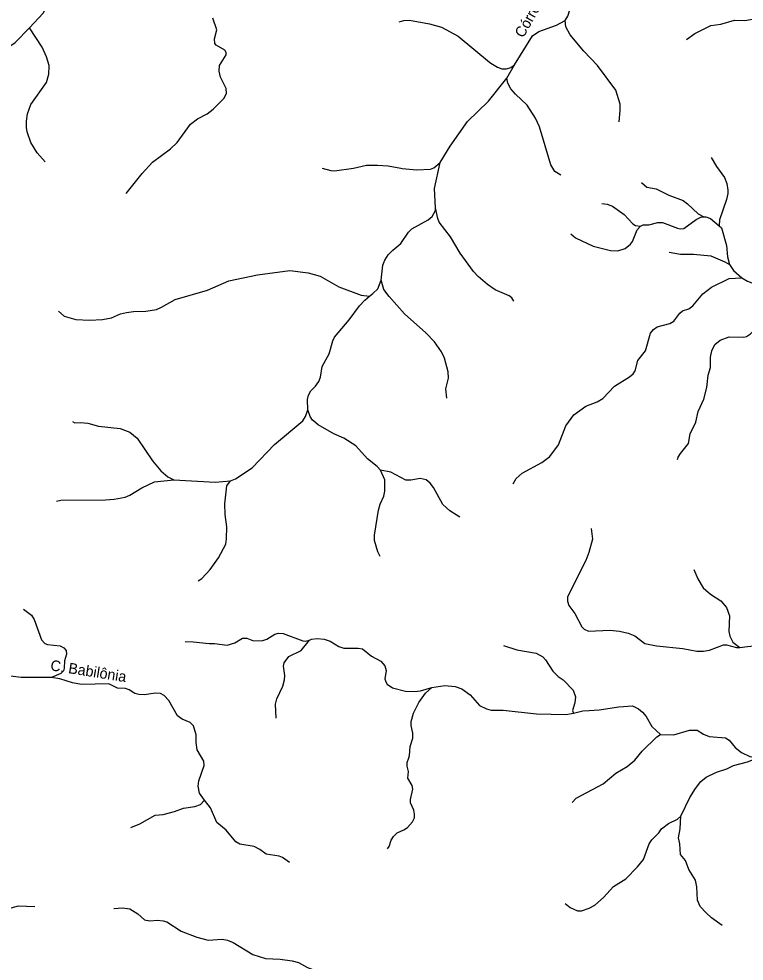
# Model space of a CAD drawing. Extents: x 473.9 to 500, y 7733.1 to 7760.8.
# Drawn here: x 481.99 to 487.45, y 7741.31 to 7748.41 of the extents above; entities that cross this region are included whole.
import ezdxf
from ezdxf.enums import TextEntityAlignment as Align

# ---------------------------------------------------------------- set-up
doc = ezdxf.new("R2010")
doc.units = 0
doc.header["$LTSCALE"] = 0.032
doc.layers.add('61', color=7, linetype='Continuous')
doc.layers.add('7', color=7, linetype='Continuous', lineweight=25)

msp = doc.modelspace()

# ---------------------------------------------------------------- linework, layer by layer
at = {"layer": '7'}
msp.add_line((485.6657, 7747.9601), (485.7235, 7748.059), dxfattribs=at)
for points in [[(482.0709, 7748.3392), (482.1724, 7748.4494), (482.2191, 7748.5344), (482.2567, 7748.7095), (482.2852, 7748.8048), (482.3234, 7748.9022), (482.3735, 7748.9927), (482.4026, 7749.0943), (482.4125, 7749.1288), (482.4697, 7749.2448), (482.5611, 7749.4699), (482.8029, 7749.7518), (482.8852, 7749.8245), (482.9562, 7749.915), (483.033, 7749.996), (483.0934, 7750.0378)], [(486.1039, 7748.3931), (486.126, 7748.4265), (486.1396, 7748.4732), (486.1532, 7748.5626), (486.1581, 7748.6544), (486.1533, 7748.8298), (486.1684, 7748.907), (486.2202, 7749.0114), (486.3188, 7749.1595)], [(487.0191, 7748.2502), (487.0804, 7748.2965), (487.2027, 7748.3564), (487.2773, 7748.3661), (487.3794, 7748.3957), (487.4572, 7748.3934), (487.5013, 7748.4013), (487.615, 7748.4076), (487.6676, 7748.4312), (487.7, 7748.4595)], [(482.7989, 7747.091), (482.9192, 7747.2406), (482.9962, 7747.3258), (483.1313, 7747.4264), (483.1816, 7747.4742), (483.2826, 7747.6137), (483.3348, 7747.6528), (483.4092, 7747.69), (483.4542, 7747.7253), (483.5343, 7747.8062), (483.5554, 7747.845), (483.551, 7747.8823), (483.5102, 7747.9667), (483.4977, 7748.0117), (483.5015, 7748.0559), (483.552, 7748.135), (483.5522, 7748.1524), (483.5407, 7748.1707), (483.4758, 7748.2084), (483.4673, 7748.2213), (483.4641, 7748.257), (483.4801, 7748.3227), (483.4505, 7748.4106)], [(484.8535, 7748.3833), (484.8909, 7748.3941), (484.9313, 7748.3973), (485.0833, 7748.3677), (485.1741, 7748.3434), (485.2991, 7748.2756), (485.5358, 7748.0801), (485.5452, 7748.0723), (485.596, 7748.0418), (485.6276, 7748.0302), (485.6635, 7748.0307), (485.6969, 7748.0389), (485.7235, 7748.059)], [(485.7235, 7748.059), (485.8587, 7748.2777), (485.9071, 7748.3115), (486.0397, 7748.3581), (486.1039, 7748.3931)], [(486.5116, 7747.6293), (486.5204, 7747.715), (486.5188, 7747.7647), (486.4874, 7747.8694), (486.3483, 7748.0555), (486.2444, 7748.1628), (486.143, 7748.2871), (486.1103, 7748.3463), (486.1039, 7748.3931)], [(481.7151, 7747.8935), (481.7306, 7747.902), (481.7418, 7747.9179), (481.8131, 7748.078), (481.8468, 7748.1401), (481.8712, 7748.1642), (481.962, 7748.227), (482.0709, 7748.3392)], [(482.1896, 7747.3284), (482.1274, 7747.3957), (482.0805, 7747.4738), (482.053, 7747.5547), (482.0466, 7747.5868), (482.0466, 7747.6358), (482.0546, 7747.6909), (482.0804, 7747.7602), (482.1975, 7747.9272), (482.2149, 7747.9905), (482.2189, 7748.0507), (482.2177, 7748.0548), (482.1986, 7748.1198), (482.1664, 7748.1922), (482.0709, 7748.3392)], [(485.1625, 7747.3234), (485.2377, 7747.4478), (485.3705, 7747.6338), (485.5276, 7747.7853), (485.6657, 7747.9601)], [(486.0735, 7747.2288), (486.0261, 7747.2552), (485.9964, 7747.3071), (485.9108, 7747.5916), (485.8806, 7747.6572), (485.8187, 7747.7562), (485.7297, 7747.8395), (485.6948, 7747.8799), (485.6741, 7747.9223), (485.6657, 7747.9601)], [(487.2043, 7747.3617), (487.2443, 7747.2939), (487.3046, 7747.2116), (487.3215, 7747.1647), (487.3302, 7747.1155), (487.3303, 7747.0915), (487.3191, 7747.045), (487.267, 7746.8926), (487.2646, 7746.8488), (487.2645, 7746.8475)], [(484.2749, 7747.2816), (484.3393, 7747.2629), (484.3679, 7747.2621), (484.5115, 7747.2821), (484.6094, 7747.303), (484.6923, 7747.3046), (484.7729, 7747.2996), (484.8676, 7747.2806), (484.8762, 7747.2789), (484.988, 7747.2693), (485.0912, 7747.2734), (485.1165, 7747.2833), (485.1625, 7747.3234)], [(485.1284, 7746.9822), (485.1205, 7747.1281), (485.1625, 7747.3234)], [(486.6789, 7747.1723), (486.7209, 7747.1386), (486.7911, 7747.1249), (486.8855, 7747.0783), (486.9925, 7747.0388), (487.027, 7747.0136), (487.1068, 7746.9363), (487.1501, 7746.914)], [(486.3813, 7747.0145), (486.4224, 7747.0108), (486.4625, 7746.9944), (486.5505, 7746.9328), (486.6134, 7746.8609), (486.635, 7746.85), (486.6721, 7746.8451)], [(484.7181, 7746.4386), (484.7326, 7746.5496), (484.746, 7746.5874), (484.771, 7746.6273), (484.806, 7746.6644), (484.8665, 7746.7129), (484.9255, 7746.7991), (484.951, 7746.824), (485.0727, 7746.8933), (485.1027, 7746.9178), (485.1279, 7746.962), (485.1284, 7746.9822)], [(485.7178, 7746.2781), (485.7026, 7746.3044), (485.682, 7746.3201), (485.5772, 7746.3658), (485.5193, 7746.4041), (485.4493, 7746.4642), (485.4151, 7746.5017), (485.3133, 7746.6397), (485.2416, 7746.764), (485.1565, 7746.8734), (485.1448, 7746.9013), (485.1284, 7746.9822)], [(486.6721, 7746.8451), (486.6921, 7746.8553), (486.7349, 7746.854), (486.804, 7746.8731), (486.8379, 7746.8731), (486.9505, 7746.8289), (486.9723, 7746.8235), (486.9979, 7746.8265), (487.0911, 7746.8957), (487.1265, 7746.9115), (487.1501, 7746.914)], [(487.1501, 7746.914), (487.1646, 7746.9155), (487.1989, 7746.9028), (487.2645, 7746.8475)], [(486.1466, 7746.7857), (486.183, 7746.7577), (486.3155, 7746.6935), (486.4454, 7746.6598), (486.5017, 7746.6589), (486.556, 7746.6761), (486.5972, 7746.7093), (486.611, 7746.7288), (486.6472, 7746.816), (486.6721, 7746.8451)], [(487.2645, 7746.8475), (487.2837, 7746.8313), (487.3207, 7746.6996), (487.3287, 7746.6127), (487.3429, 7746.5548)], [(486.8887, 7746.6487), (486.9749, 7746.6327), (487.0708, 7746.6343), (487.2033, 7746.6198), (487.3065, 7746.5763), (487.3429, 7746.5548)], [(482.2896, 7746.2045), (482.3309, 7746.1673), (482.4202, 7746.1404), (482.5211, 7746.1355), (482.6199, 7746.1404), (482.689, 7746.1545), (482.7548, 7746.1844), (482.8018, 7746.1948), (482.8526, 7746.202), (482.9461, 7746.2029), (483.026, 7746.2172), (483.0644, 7746.2331), (483.1671, 7746.2925), (483.4114, 7746.3631), (483.5706, 7746.4331), (483.7873, 7746.4785), (484.0305, 7746.5099), (484.1696, 7746.4939), (484.2601, 7746.468), (484.3999, 7746.3884), (484.5673, 7746.324), (484.6323, 7746.3159)], [(487.3429, 7746.5548), (487.3721, 7746.5113), (487.4365, 7746.4549)], [(484.6323, 7746.3159), (484.6563, 7746.3374), (484.6948, 7746.3721), (484.7181, 7746.4386)], [(485.2132, 7745.548), (485.2056, 7745.6185), (485.2264, 7745.699), (485.2231, 7745.7474), (485.1965, 7745.8507), (485.1728, 7745.8987), (485.1201, 7745.9717), (485.0566, 7746.0415), (484.895, 7746.183), (484.7784, 7746.3143), (484.7388, 7746.3675), (484.7181, 7746.4386)], [(485.7141, 7744.9039), (485.7363, 7744.9431), (485.781, 7744.9836), (485.9289, 7745.0633), (485.9885, 7745.1099), (486.0554, 7745.1975), (486.1096, 7745.3411), (486.1699, 7745.4233), (486.2601, 7745.4889), (486.3462, 7745.5216), (486.3895, 7745.545), (486.4766, 7745.6396), (486.5905, 7745.7083), (486.6174, 7745.7325), (486.6311, 7745.7541), (486.6529, 7745.8311), (486.7096, 7745.9062), (486.7465, 7746.039), (486.7704, 7746.0671), (486.7979, 7746.0851), (486.8933, 7746.1108), (486.9227, 7746.1289), (486.9688, 7746.1893), (486.9897, 7746.2058), (487.0355, 7746.2222), (487.0671, 7746.2435), (487.1416, 7746.3357), (487.2062, 7746.3851), (487.3402, 7746.4491), (487.4365, 7746.4549)], [(487.4365, 7746.4549), (487.4787, 7746.4305), (487.5926, 7746.3836), (487.6609, 7746.3373), (487.7328, 7746.2653)], [(484.1661, 7745.4612), (484.1649, 7745.5396), (484.1711, 7745.5723), (484.1884, 7745.6049), (484.2237, 7745.6379), (484.2503, 7745.6747), (484.2627, 7745.7077), (484.2748, 7745.7862), (484.3277, 7745.8824), (484.3552, 7745.981), (484.3686, 7746.0091), (484.4772, 7746.1385), (484.5559, 7746.2435), (484.5952, 7746.286), (484.6323, 7746.3159)], [(486.9514, 7745.0862), (486.9552, 7745.1044), (486.974, 7745.1325), (487.0331, 7745.206), (487.0468, 7745.2802), (487.0879, 7745.3684), (487.1077, 7745.447), (487.1489, 7745.5419), (487.1731, 7745.6287), (487.1825, 7745.7223), (487.2003, 7745.7808), (487.2004, 7745.858), (487.2104, 7745.9056), (487.2323, 7745.9524), (487.2728, 7745.9865), (487.3399, 7746.0096), (487.4483, 7746.0089), (487.4707, 7746.0142), (487.5, 7746.0343), (487.565, 7746.1024), (487.6346, 7746.2048), (487.6801, 7746.2431), (487.7328, 7746.2653)], [(483.5846, 7744.9259), (483.6222, 7744.9397), (483.7485, 7745.0248), (483.9166, 7745.2), (484.1285, 7745.3776), (484.1503, 7745.4104), (484.1661, 7745.4612)], [(484.7153, 7745.0066), (484.6894, 7745.0346), (484.6168, 7745.0902), (484.5282, 7745.1883), (484.4384, 7745.2459), (484.3617, 7745.2802), (484.244, 7745.3477), (484.2113, 7745.3742), (484.2015, 7745.3821), (484.1831, 7745.4094), (484.1661, 7745.4612)], [(482.3933, 7745.3721), (482.4115, 7745.3624), (482.4554, 7745.3648), (482.509, 7745.3592), (482.5901, 7745.3386), (482.7537, 7745.3192), (482.8258, 7745.2928), (482.8816, 7745.2474), (482.9967, 7745.0766), (483.0587, 7744.9998), (483.1111, 7744.957), (483.1568, 7744.9321)], [(484.7115, 7744.3551), (484.6938, 7744.3899), (484.67, 7744.4758), (484.6684, 7744.5154), (484.6984, 7744.7051), (484.7106, 7744.751), (484.7385, 7744.8096), (484.7478, 7744.8485), (484.7469, 7744.9344), (484.7153, 7745.0066)], [(485.3109, 7744.6528), (485.2352, 7744.6995), (485.1845, 7744.747), (485.1143, 7744.8757), (485.0891, 7744.9072), (485.058, 7744.9328), (485.0123, 7744.9425), (484.9414, 7744.9303), (484.9037, 7744.9313), (484.7909, 7744.9903), (484.7153, 7745.0066)], [(482.2741, 7744.7715), (482.3065, 7744.7805), (482.6423, 7744.7821), (482.7091, 7744.7881), (482.7907, 7744.8035), (482.827, 7744.8187), (482.9172, 7744.8735), (483.0122, 7744.9192), (483.1568, 7744.9321)], [(483.1568, 7744.9321), (483.469, 7744.9167), (483.5846, 7744.9259)], [(483.3398, 7744.1711), (483.3692, 7744.1889), (483.4303, 7744.2583), (483.495, 7744.3463), (483.549, 7744.4494), (483.5554, 7744.4897), (483.5571, 7744.5798), (483.5443, 7744.6727), (483.5427, 7744.752), (483.5573, 7744.887), (483.5846, 7744.9259)], [(486.3004, 7744.5664), (486.3112, 7744.4867), (486.2835, 7744.3855), (486.2604, 7744.326), (486.1228, 7744.0524), (486.1221, 7744.0194), (486.1325, 7743.9859), (486.1769, 7743.9268), (486.2317, 7743.8253), (486.2489, 7743.8075), (486.2805, 7743.7926), (486.4413, 7743.7999), (486.5131, 7743.7934), (486.5792, 7743.7792), (486.6293, 7743.7573), (486.7053, 7743.7011), (486.7924, 7743.6821), (486.9916, 7743.6621), (487.0971, 7743.6436), (487.1464, 7743.642), (487.1929, 7743.6497), (487.2963, 7743.69), (487.3206, 7743.69), (487.3949, 7743.6701), (487.4196, 7743.6711)], [(487.0734, 7744.2585), (487.1043, 7744.1866), (487.1456, 7744.1185), (487.2006, 7744.0716), (487.2771, 7744.0222), (487.3195, 7743.9705), (487.3416, 7743.9094), (487.3383, 7743.79), (487.346, 7743.7558), (487.3676, 7743.7106), (487.4196, 7743.6711)], [(482.0261, 7743.9583), (482.0845, 7743.9134), (482.1046, 7743.8799), (482.1602, 7743.7272), (482.186, 7743.7013), (482.2063, 7743.693), (482.3022, 7743.6834), (482.3298, 7743.6674), (482.3456, 7743.6476), (482.3496, 7743.6191), (482.3344, 7743.5685), (482.3319, 7743.5137), (482.3255, 7743.4945), (482.3056, 7743.4741), (482.2368, 7743.4441)], [(483.2428, 7743.7148), (483.3043, 7743.7133), (483.4238, 7743.6989), (483.463, 7743.7004), (483.559, 7743.6869), (483.6161, 7743.706), (483.6754, 7743.7399), (483.7068, 7743.7396), (483.7587, 7743.7214), (483.8278, 7743.7224), (483.8591, 7743.7336), (483.9171, 7743.7715), (483.9453, 7743.7783), (483.982, 7743.7758), (484.1287, 7743.7209), (484.1469, 7743.7177), (484.1805, 7743.7242)], [(484.1805, 7743.7242), (484.1956, 7743.7319), (484.2367, 7743.7381), (484.2896, 7743.7334), (484.3348, 7743.7166), (484.3999, 7743.6775), (484.4387, 7743.6653), (484.5462, 7743.6661), (484.5785, 7743.6596), (484.6466, 7743.6044), (484.7158, 7743.5662), (484.7461, 7743.5321), (484.7566, 7743.4956), (484.747, 7743.435), (484.7539, 7743.4117), (484.7639, 7743.3934), (484.8033, 7743.3668), (484.9033, 7743.3405), (484.9689, 7743.3373), (485.0153, 7743.3427), (485.1012, 7743.3679)], [(483.9284, 7743.137), (483.9228, 7743.2429), (483.9329, 7743.2821), (483.9786, 7743.3783), (483.9916, 7743.4273), (483.9932, 7743.4594), (483.9845, 7743.5303), (483.988, 7743.5544), (484.0248, 7743.602), (484.1164, 7743.6478), (484.1805, 7743.7242)], [(485.6393, 7743.6857), (485.7417, 7743.6533), (485.8867, 7743.6268), (485.9378, 7743.6008), (485.958, 7743.5776), (486.0114, 7743.4906), (486.0512, 7743.4522), (486.0894, 7743.4268), (486.1656, 7743.3495), (486.1822, 7743.2991), (486.1783, 7743.253), (486.1597, 7743.1965), (486.167, 7743.1758)], [(487.4196, 7743.6711), (487.4771, 7743.677), (487.5563, 7743.6852), (487.6237, 7743.6844), (487.7049, 7743.6717), (487.8022, 7743.6311), (487.9952, 7743.5831), (488.0989, 7743.5365), (488.1381, 7743.5258), (488.1824, 7743.5234), (488.2518, 7743.537), (488.2972, 7743.5291)], [(482.2368, 7743.4441), (482.0066, 7743.4435), (481.8239, 7743.4671), (481.5727, 7743.476), (481.4942, 7743.4897), (481.3935, 7743.496), (481.3486, 7743.4871), (481.273, 7743.4428), (481.2278, 7743.4288)], [(483.3882, 7742.5188), (483.352, 7742.5721), (483.3406, 7742.6265), (483.3468, 7742.6643), (483.3855, 7742.7808), (483.3839, 7742.8145), (483.3327, 7742.8978), (483.3246, 7742.9534), (483.3245, 7743.012), (483.3053, 7743.0791), (483.2797, 7743.1046), (483.221, 7743.1301), (483.1856, 7743.154), (483.1195, 7743.2713), (483.0854, 7743.3095), (483.0574, 7743.3242), (483.0177, 7743.326), (482.937, 7743.3144), (482.8929, 7743.3149), (482.8646, 7743.3235), (482.8557, 7743.3292), (482.82, 7743.3521), (482.7929, 7743.3604), (482.7341, 7743.3646), (482.6667, 7743.3969), (482.4619, 7743.391), (482.3942, 7743.4047), (482.2994, 7743.4348), (482.2368, 7743.4441)], [(485.1012, 7743.3679), (485.1984, 7743.3845), (485.2758, 7743.3774), (485.3277, 7743.358), (485.3905, 7743.3143), (485.46, 7743.2336), (485.5122, 7743.2073), (485.5484, 7743.1987), (485.6381, 7743.1969), (485.8892, 7743.1691), (486.1112, 7743.1657), (486.167, 7743.1758)], [(484.7665, 7742.1537), (484.7782, 7742.1706), (484.7933, 7742.2178), (484.8116, 7742.2458), (484.8405, 7742.2726), (484.8894, 7742.2952), (484.9167, 7742.3148), (484.954, 7742.357), (484.9698, 7742.3867), (484.9714, 7742.4155), (484.9652, 7742.4435), (484.941, 7742.5003), (484.9411, 7742.5248), (484.9586, 7742.603), (484.9517, 7742.6295), (484.9204, 7742.6868), (484.9249, 7742.7356), (484.9138, 7742.7754), (484.9154, 7742.8038), (484.9275, 7742.8385), (484.9337, 7742.8562), (484.9366, 7742.923), (484.9586, 7742.9862), (484.9586, 7743.0249), (484.9458, 7743.082), (484.9458, 7743.1118), (484.9621, 7743.1759), (485.002, 7743.2555), (485.053, 7743.3258), (485.1012, 7743.3679)], [(486.167, 7743.1758), (486.2382, 7743.1929), (486.2857, 7743.1954), (486.3617, 7743.1993), (486.5096, 7743.2235), (486.6109, 7743.2305), (486.6583, 7743.2082), (486.6886, 7743.182), (486.7139, 7743.1506), (486.7575, 7743.0749), (486.8241, 7743.0156)], [(486.1566, 7742.5033), (486.1889, 7742.5342), (486.3922, 7742.6438), (486.4855, 7742.7244), (486.5721, 7742.7722), (486.6292, 7742.8222), (486.6846, 7742.888), (486.7965, 7742.9975), (486.8241, 7743.0156)], [(486.8241, 7743.0156), (486.9234, 7743.0132), (487.0413, 7743.047), (487.0983, 7743.048), (487.146, 7743.018), (487.1898, 7742.9996), (487.3129, 7742.9884), (487.3397, 7742.971), (487.3862, 7742.9165), (487.4319, 7742.8783), (487.4957, 7742.8481), (487.5561, 7742.838)], [(486.9771, 7742.4003), (487.045, 7742.539), (487.0859, 7742.6079), (487.1266, 7742.6614), (487.167, 7742.6939), (487.245, 7742.7315), (487.3216, 7742.7566), (487.3729, 7742.7822), (487.4788, 7742.8085), (487.5561, 7742.838)], [(482.8331, 7742.3139), (482.9021, 7742.3411), (483.0159, 7742.4069), (483.0764, 7742.4113), (483.1629, 7742.4343), (483.2313, 7742.46), (483.3144, 7742.4728), (483.3572, 7742.4882), (483.3882, 7742.5188)], [(484.0279, 7742.0491), (483.9756, 7742.0873), (483.9505, 7742.0983), (483.8535, 7742.1131), (483.8056, 7742.1482), (483.7615, 7742.1698), (483.6555, 7742.1874), (483.6241, 7742.2047), (483.5524, 7742.2931), (483.4824, 7742.3516), (483.4336, 7742.4617), (483.3882, 7742.5188)], [(486.1051, 7741.7419), (486.1422, 7741.7121), (486.1976, 7741.685), (486.2268, 7741.6864), (486.2866, 7741.7054), (486.3274, 7741.7299), (486.3946, 7741.7866), (486.4685, 7741.8691), (486.5621, 7741.9261), (486.6507, 7742.0172), (486.6943, 7742.0726), (486.7364, 7742.1896), (486.7575, 7742.2201), (486.8109, 7742.2728), (486.8317, 7742.3048), (486.8836, 7742.3434), (486.9515, 7742.3755), (486.9771, 7742.4003)], [(487.2886, 7741.5761), (487.2063, 7741.6333), (487.1667, 7741.6712), (487.1225, 7741.7195), (487.1007, 7741.767), (487.0961, 7741.8671), (487.0865, 7741.9179), (487.0365, 7741.9982), (487.0125, 7742.0644), (486.9746, 7742.1102), (486.9694, 7742.1917), (486.9575, 7742.2367), (486.9703, 7742.3036), (486.9771, 7742.4003)], [(482.1099, 7741.7153), (481.984, 7741.7217), (481.7828, 7741.6667), (481.7217, 7741.6213), (481.6941, 7741.5852), (481.6778, 7741.5085), (481.6894, 7741.3158), (481.7178, 7741.266), (481.7194, 7741.228), (481.6886, 7741.1924)], [(482.7052, 7741.7027), (482.7719, 7741.7088), (482.8259, 7741.7005), (482.8866, 7741.6633), (482.9371, 7741.6172), (482.9774, 7741.6102), (483.0334, 7741.615), (483.0776, 7741.6118), (483.1055, 7741.6026), (483.2118, 7741.5318), (483.3296, 7741.4866), (483.4169, 7741.466), (483.5224, 7741.4723), (483.5616, 7741.4644), (483.6052, 7741.4474), (483.7526, 7741.3582), (483.8467, 7741.3279), (483.9579, 7741.3224), (484.0477, 7741.3087), (484.0961, 7741.2966), (484.1635, 7741.2601), (484.2055, 7741.2445), (484.2731, 7741.2289)]]:
    msp.add_lwpolyline(points, dxfattribs=at)

# ---------------------------------------------------------------- texts
at = {"layer": '61'}
for s, rotation, p in [('Córrego Pinhão', 60.751, (485.9729, 7748.5846)), ('C. Babilônia', 351.027, (482.5086, 7743.4537))]:
    msp.add_text(s, height=0.08, rotation=rotation, dxfattribs=at).set_placement(p, align=Align.CENTER)

doc.saveas('drawing.dxf')
